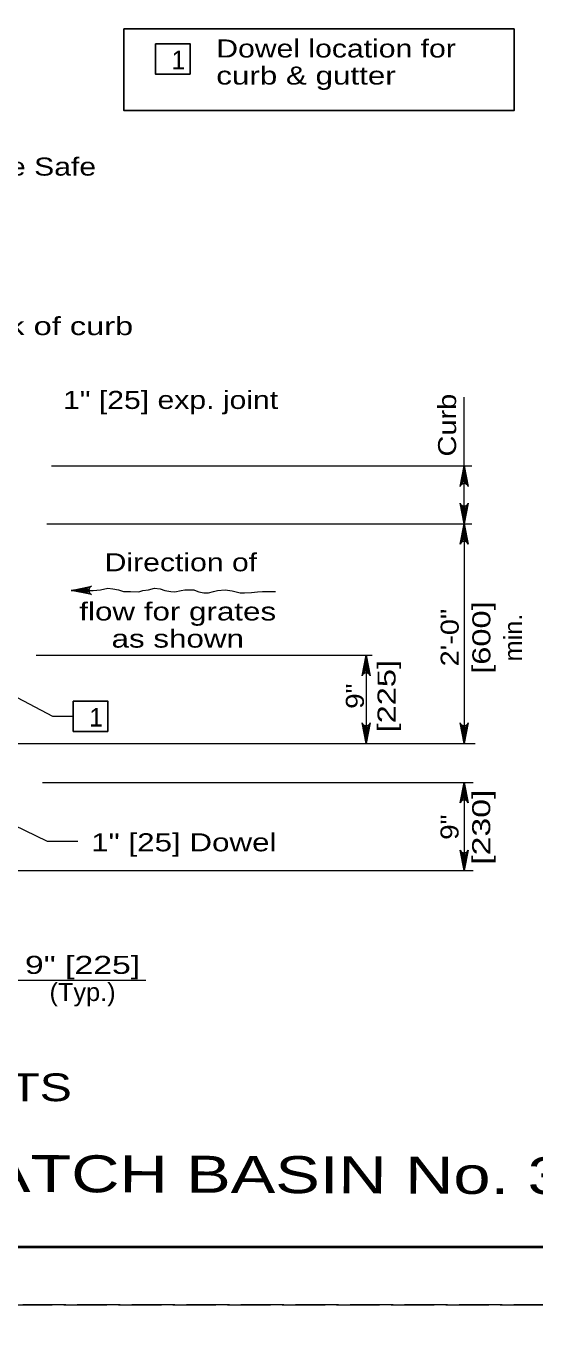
# Model space of a CAD drawing. Extents: x 1352.5 to 1386.5, y 735.9 to 779.9.
# Drawn here: x 1367.76 to 1372.16, y 757.67 to 768.97 of the extents above; entities that cross this region are included whole.
import ezdxf
from ezdxf.enums import TextEntityAlignment as Align

# ---------------------------------------------------------------- set-up
doc = ezdxf.new("R2010")
doc.units = 0
doc.header["$LTSCALE"] = 0.062
doc.linetypes.add('LONG_DASHED', pattern=[7.5, 6, -1.5])
doc.layers.add('1', color=7, linetype='Continuous', lineweight=13)

msp = doc.modelspace()

# ---------------------------------------------------------------- linework, layer by layer
at = {"layer": '1'}
for p, q in [((1371.5525, 764.67258), (1371.5525, 765.76725)), ((1367.98058, 765.17233), (1371.61917, 765.17233)), ((1371.52775, 765.01017), (1371.5525, 765.17233)), ((1371.53808, 765.01633), (1371.5525, 765.17233)), ((1371.5525, 765.01917), (1371.5525, 765.17233)), ((1371.56383, 765.0175), (1371.5525, 765.17233)), ((1371.57492, 765.01208), (1371.5525, 765.17233)), ((1371.53008, 764.83283), (1371.5525, 764.67258)), ((1371.54117, 764.82742), (1371.5525, 764.67258)), ((1371.57725, 764.83475), (1371.5525, 764.67258)), ((1371.56692, 764.82858), (1371.5525, 764.67258)), ((1371.5525, 764.82575), (1371.5525, 764.67258)), ((1367.94158, 764.67258), (1371.61917, 764.67258)), ((1371.52775, 764.5105), (1371.5525, 764.67258)), ((1371.53808, 764.51658), (1371.5525, 764.67258)), ((1371.5525, 764.67258), (1371.5525, 762.77367)), ((1371.5525, 764.51942), (1371.5525, 764.67258)), ((1371.56383, 764.51775), (1371.5525, 764.67258)), ((1371.57492, 764.51233), (1371.5525, 764.67258)), ((1368.31217, 764.11883), (1368.15192, 764.09642)), ((1368.30675, 764.10775), (1368.15192, 764.09642)), ((1368.30508, 764.09642), (1368.15192, 764.09642)), ((1368.30792, 764.08208), (1368.15192, 764.09642)), ((1368.31408, 764.07167), (1368.15192, 764.09642)), ((1367.85058, 763.53575), (1370.75767, 763.53575)), ((1370.67942, 763.37358), (1370.70425, 763.53575)), ((1370.68983, 763.37975), (1370.70425, 763.53575)), ((1370.70425, 763.53575), (1370.70425, 762.96183)), ((1370.70425, 763.38258), (1370.70425, 763.53575)), ((1370.71558, 763.38092), (1370.70425, 763.53575)), ((1370.72667, 763.3755), (1370.70425, 763.53575)), ((1370.70425, 763.01033), (1370.70425, 762.77367)), ((1370.68183, 762.93392), (1370.70425, 762.77367)), ((1370.69292, 762.9285), (1370.70425, 762.77367)), ((1370.729, 762.93583), (1370.70425, 762.77367)), ((1370.71867, 762.92967), (1370.70425, 762.77367)), ((1370.70425, 762.92683), (1370.70425, 762.77367)), ((1371.53008, 762.93392), (1371.5525, 762.77367)), ((1371.54117, 762.9285), (1371.5525, 762.77367)), ((1371.57725, 762.93583), (1371.5525, 762.77367)), ((1371.56692, 762.92967), (1371.5525, 762.77367)), ((1371.5525, 762.92683), (1371.5525, 762.77367)), ((1366.99225, 762.77367), (1371.64892, 762.77367)), ((1367.90258, 762.43642), (1371.63117, 762.43642)), ((1371.52775, 762.27425), (1371.5525, 762.43642)), ((1371.53808, 762.28042), (1371.5525, 762.43642)), ((1371.5525, 762.28325), (1371.5525, 762.43642)), ((1371.56383, 762.28158), (1371.5525, 762.43642)), ((1371.57492, 762.27617), (1371.5525, 762.43642)), ((1371.53008, 761.83458), (1371.5525, 761.67433)), ((1371.54117, 761.82917), (1371.5525, 761.67433)), ((1371.57725, 761.8365), (1371.5525, 761.67433)), ((1371.56692, 761.83033), (1371.5525, 761.67433)), ((1371.5525, 761.8275), (1371.5525, 761.67433)), ((1366.89875, 761.67433), (1371.63117, 761.67433)), ((1366.78067, 760.72767), (1368.79867, 760.72767))]:
    msp.add_line(p, q, dxfattribs=at)
at = {"layer": '1', "linetype": 'LONG_DASHED'}
for points in [[(1352.513, 757.91967), (1386.513, 757.91967), (1386.513, 779.91967), (1352.513, 779.91967)], [(1352.513, 735.91967), (1386.513, 735.91967), (1386.513, 757.91967), (1352.513, 757.91967)]]:
    msp.add_lwpolyline(points, close=True, dxfattribs=at)
at = {"layer": '1', "lineweight": 25}
msp.add_lwpolyline([(1386.013, 758.41967), (1354.513, 758.41967), (1354.513, 779.41967)], dxfattribs=at)
at = {"layer": '1', "lineweight": 40}
msp.add_lwpolyline([(1354.513, 779.41967), (1386.013, 779.41967), (1386.013, 758.41967), (1354.513, 758.41967)], close=True, dxfattribs=at)
msp.add_lwpolyline([(1354.513, 779.41967), (1386.013, 779.41967), (1386.013, 758.41967), (1354.513, 758.41967)], close=True, dxfattribs=at)
at = {"layer": '1', "lineweight": 25}
for points in [[(1368.60892, 768.94975), (1371.98425, 768.94975), (1371.98425, 768.244), (1368.60892, 768.244)], [(1368.88142, 768.82042), (1368.88142, 768.55875), (1369.18025, 768.55875), (1369.18025, 768.82042)], [(1368.16958, 763.13858), (1368.16958, 762.87692), (1368.46842, 762.87692), (1368.46842, 763.13858)]]:
    msp.add_lwpolyline(points, close=True, dxfattribs=at)
at = {"layer": '1'}
for points in [[(1371.51708, 764.99533), (1371.5525, 765.17233), (1371.58792, 764.99533)], [(1371.58792, 764.84958), (1371.5525, 764.67258), (1371.51708, 764.84958)], [(1371.51708, 764.49558), (1371.5525, 764.67258), (1371.58792, 764.49558)], [(1368.32892, 764.061), (1368.15192, 764.09642), (1368.32892, 764.13183)], [(1368.15192, 764.09642), (1368.34133, 764.09642), (1368.406, 764.101), (1368.47067, 764.11475), (1368.51375, 764.11017), (1368.56125, 764.101), (1368.60433, 764.08733), (1368.66475, 764.08733), (1368.73808, 764.08275), (1368.7725, 764.09642), (1368.82, 764.101), (1368.87175, 764.11475), (1368.9235, 764.11017), (1368.96225, 764.09642), (1369.014, 764.08733), (1369.0485, 764.08275), (1369.10458, 764.09642), (1369.13467, 764.101), (1369.16925, 764.101), (1369.21233, 764.101), (1369.23392, 764.09192), (1369.2555, 764.08275), (1369.29858, 764.07358), (1369.34167, 764.07358), (1369.38483, 764.08733), (1369.41933, 764.09642), (1369.484, 764.101), (1369.54442, 764.09192), (1369.61342, 764.07358), (1369.65217, 764.07358), (1369.7125, 764.07817), (1369.76425, 764.08275), (1369.80742, 764.08733), (1369.89358, 764.08733), (1369.9195, 764.08733)], [(1367.07508, 763.49067), (1367.99117, 763.00975), (1368.16958, 763.00975)], [(1370.66883, 763.35875), (1370.70425, 763.53575), (1370.73967, 763.35875)], [(1370.73967, 762.95067), (1370.70425, 762.77367), (1370.66883, 762.95067)], [(1371.58792, 762.95067), (1371.5525, 762.77367), (1371.51708, 762.95067)], [(1371.51708, 762.25942), (1371.5525, 762.43642), (1371.58792, 762.25942)], [(1371.5525, 762.43642), (1371.5525, 761.90558), (1371.5525, 761.67433)], [(1366.98408, 762.39283), (1367.94567, 761.92742), (1368.20933, 761.92742)], [(1371.58792, 761.85133), (1371.5525, 761.67433), (1371.51708, 761.85133)]]:
    msp.add_lwpolyline(points, dxfattribs=at)
for centre, start, end in [((1371.55255, 764.98102), 22.08782, 157.91395), ((1371.55247, 764.8639), 202.08782, 337.91395), ((1371.55255, 764.48131), 22.08782, 157.91395), ((1368.34322, 764.09648), 112.08782, 247.91395), ((1370.70427, 763.34446), 22.08782, 157.91395), ((1370.70419, 762.96499), 202.08782, 337.91395), ((1371.55247, 762.96499), 202.08782, 337.91395), ((1371.55255, 762.2451), 22.08782, 157.91395), ((1371.55247, 761.86563), 202.08782, 337.91395)]:
    msp.add_arc(centre, 0.0382, start, end, dxfattribs=at)

# ---------------------------------------------------------------- texts
for s, height, width, p in [('Dowel location for', 0.156, 1.25, (1369.40767, 768.70225)), ('curb & gutter', 0.156, 1.3, (1369.40767, 768.46825)), ('Grate (Bicycle Safe', 0.156, 1.25, (1366.12158, 767.68117)), ('Back of curb', 0.156, 1.35, (1367.12317, 766.30267)), ('1" [25] Dowel', 0.156, 1.3, (1368.325, 761.8405)), ('PLAN OF CATCH BASIN AND PAVEMENT JOINTS', 0.24, 1.3, (1358.44475, 759.68083))]:
    msp.add_text(s, height=height, dxfattribs=dict(at, width=width)).set_placement(p)
for p in [(1369.02025, 768.60117), (1368.30842, 762.91942)]:
    msp.add_text('1', height=0.16, dxfattribs=at).set_placement(p)
for s, width, p in [('1" [25] exp. joint', 1.25, (1369.01229, 765.66442)), ('Direction of', 1.25, (1369.10125, 764.26108)), ('flow for grates', 1.3, (1369.07417, 763.83592)), ('as shown', 1.3, (1369.07412, 763.60125)), ('9" [225]', 1.4, (1368.25054, 760.78108)), ('(Typ.)', 1.05, (1368.25062, 760.54642))]:
    msp.add_text(s, height=0.156, dxfattribs=dict(at, width=width)).set_placement(p, align=Align.CENTER)
for s, height, rotation, width, p in [('Curb', 0.156, 90, 1.2, (1371.48267, 765.25325)), ('CATCH BASIN No. 3', 0.32, 359.766, 1.35, (1366.997, 758.89842))]:
    msp.add_text(s, height=height, rotation=rotation, dxfattribs=dict(at, width=width)).set_placement(p)
for s, width, p in [('2\'-0"', 1.2, (1371.50517, 763.68804)), ('[600]', 1.35, (1371.77917, 763.68813)), ('min.', 1.05, (1372.05317, 763.68808)), ('[225]', 1.35, (1370.95883, 763.18133)), ('9"', 1.15, (1370.68483, 763.18133)), ('[230]', 1.4, (1371.77775, 762.04908)), ('9"', 1.15, (1371.50375, 762.04908))]:
    msp.add_text(s, height=0.156, rotation=90, dxfattribs=dict(at, width=width)).set_placement(p, align=Align.CENTER)

doc.saveas('drawing.dxf')
